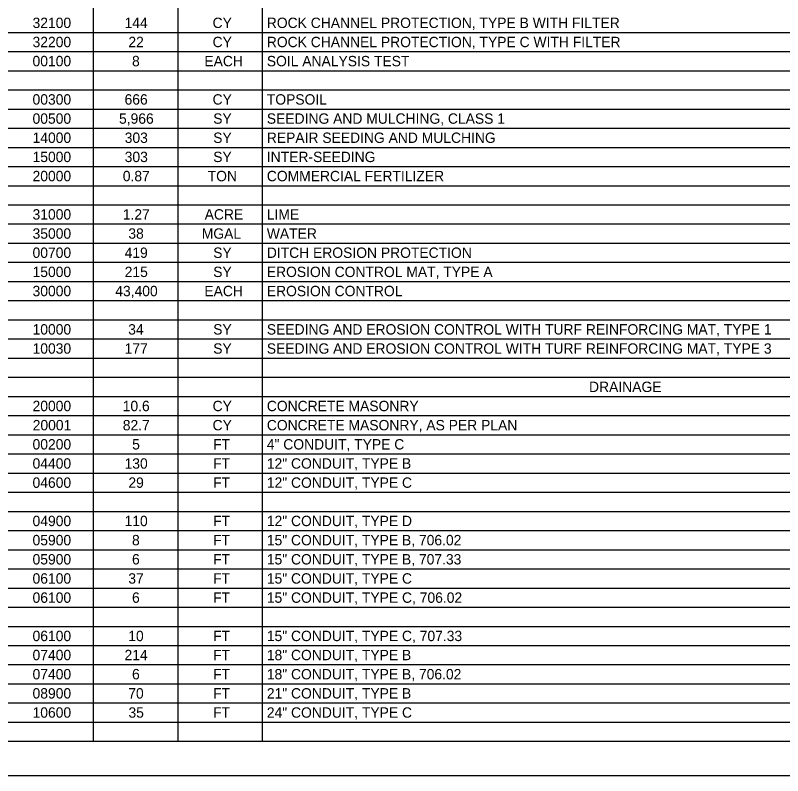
# Model space of a CAD drawing. Extents: x 0 to 34, y 0 to 22.
# Drawn here: x 16.9 to 28.11, y 0 to 11.11 of the extents above; entities that cross this region are included whole.
import ezdxf

# ---------------------------------------------------------------- set-up
doc = ezdxf.new("R2010")
doc.units = 0
for name, color, linetype in [('Default', 7, 'Continuous'), ('SH_Border', 7, 'Continuous'), ('SH_Cut_Line', 7, 'Continuous')]:
    doc.layers.add(name, color=color, linetype=linetype)

msp = doc.modelspace()

# ---------------------------------------------------------------- linework, layer by layer
at = {"layer": 'Default'}
for p, q in [((18.035, 21.5), (18.035, 0.502)), ((19.27, 21.5), (19.27, 0.502)), ((20.505, 21.5), (20.505, 0.502)), ((1.5, 10.861), (32, 10.861)), ((1.5, 10.581), (32, 10.581)), ((1.5, 10.301), (32, 10.301)), ((1.5, 10.021), (32, 10.021)), ((1.5, 9.741), (32, 9.741)), ((1.5, 9.461), (32, 9.461)), ((1.5, 9.181), (32, 9.181)), ((1.5, 8.901), (32, 8.901)), ((1.5, 8.621), (32, 8.621)), ((1.5, 8.342), (32, 8.342)), ((1.5, 8.062), (32, 8.062)), ((1.5, 7.782), (32, 7.782)), ((1.5, 7.502), (32, 7.502)), ((1.5, 7.222), (32, 7.222)), ((1.5, 6.942), (32, 6.942)), ((1.5, 6.662), (32, 6.662)), ((1.5, 6.382), (32, 6.382)), ((1.5, 6.102), (32, 6.102)), ((1.5, 5.822), (32, 5.822)), ((1.5, 5.542), (32, 5.542)), ((1.5, 5.262), (32, 5.262)), ((1.5, 4.982), (32, 4.982)), ((1.5, 4.702), (32, 4.702)), ((1.5, 4.422), (32, 4.422)), ((1.5, 4.142), (32, 4.142)), ((1.5, 3.862), (32, 3.862)), ((1.5, 3.582), (32, 3.582)), ((1.5, 3.302), (32, 3.302)), ((1.5, 3.022), (32, 3.022)), ((1.5, 2.742), (32, 2.742)), ((1.5, 2.462), (32, 2.462)), ((1.5, 2.182), (32, 2.182)), ((1.5, 1.902), (32, 1.902)), ((1.5, 1.622), (32, 1.622)), ((1.5, 1.342), (32, 1.342)), ((1.5, 1.062), (32, 1.062)), ((1.5, 0.782), (32, 0.782)), ((1.5, 0.502), (32, 0.502))]:
    msp.add_line(p, q, dxfattribs=at)
at = {"layer": 'SH_Border'}
msp.add_lwpolyline([(1.5, 21.5), (33.5, 21.5), (33.5, 0.5), (1.5, 0.5)], close=True, dxfattribs=at)
at = {"layer": 'SH_Cut_Line'}
msp.add_lwpolyline([(0, 0), (34, 0), (34, 22), (0, 22)], close=True, dxfattribs=at)

# ---------------------------------------------------------------- texts
at = {"layer": 'Default'}
for s, height, p in [('32100', 0.1515, (17.149, 10.925)), ('144', 0.1515, (18.492, 10.925)), ('CY', 0.1515, (19.779, 10.925)), ('ROCK CHANNEL PROTECTION, TYPE B WITH FILTER', 0.15151, (20.571, 10.925)), ('32200', 0.1515, (17.149, 10.645)), ('22', 0.1515, (18.549, 10.645)), ('CY', 0.1515, (19.779, 10.645)), ('ROCK CHANNEL PROTECTION, TYPE C WITH FILTER', 0.15151, (20.571, 10.645)), ('00100', 0.1515, (17.149, 10.366)), ('8', 0.152, (18.602, 10.366)), ('EACH', 0.1515, (19.659, 10.366)), ('SOIL ANALYSIS TEST', 0.15151, (20.571, 10.366)), ('00300', 0.1515, (17.149, 9.806)), ('666', 0.1515, (18.493, 9.806)), ('CY', 0.1515, (19.779, 9.806)), ('TOPSOIL', 0.1515, (20.571, 9.806)), ('00500', 0.1515, (17.149, 9.526)), ('5,966', 0.1515, (18.412, 9.526)), ('SY', 0.1515, (19.788, 9.526)), ('SEEDING AND MULCHING, CLASS 1', 0.15151, (20.571, 9.526)), ('14000', 0.1515, (17.149, 9.246)), ('303', 0.1515, (18.495, 9.246)), ('SY', 0.1515, (19.788, 9.246)), ('REPAIR SEEDING AND MULCHING', 0.15151, (20.571, 9.246)), ('15000', 0.1515, (17.149, 8.966)), ('303', 0.1515, (18.495, 8.966)), ('SY', 0.1515, (19.788, 8.966)), ('INTER-SEEDING', 0.15151, (20.571, 8.966)), ('20000', 0.1515, (17.149, 8.686)), ('0.87', 0.1515, (18.467, 8.686)), ('TON', 0.1515, (19.707, 8.686)), ('COMMERCIAL FERTILIZER', 0.15151, (20.571, 8.686)), ('31000', 0.1515, (17.149, 8.126)), ('1.27', 0.1515, (18.467, 8.126)), ('ACRE', 0.1515, (19.663, 8.126)), ('LIME', 0.1515, (20.571, 8.126)), ('35000', 0.1515, (17.149, 7.846)), ('38', 0.1515, (18.548, 7.846)), ('MGAL', 0.1515, (19.621, 7.846)), ('WATER', 0.1515, (20.571, 7.846)), ('00700', 0.1515, (17.149, 7.566)), ('419', 0.1515, (18.494, 7.566)), ('SY', 0.1515, (19.788, 7.566)), ('DITCH EROSION PROTECTION', 0.15151, (20.571, 7.566)), ('15000', 0.1515, (17.149, 7.286)), ('215', 0.1515, (18.495, 7.286)), ('SY', 0.1515, (19.788, 7.286)), ('EROSION CONTROL MAT, TYPE A', 0.15151, (20.571, 7.286)), ('30000', 0.1515, (17.149, 7.006)), ('43,400', 0.1515, (18.357, 7.006)), ('EACH', 0.1515, (19.659, 7.006)), ('EROSION CONTROL', 0.15151, (20.571, 7.006)), ('10000', 0.1515, (17.149, 6.446)), ('34', 0.1515, (18.546, 6.446)), ('SY', 0.1515, (19.788, 6.446)), ('SEEDING AND EROSION CONTROL WITH TURF REINFORCING MAT, TYPE 1', 0.15151, (20.571, 6.446)), ('10030', 0.1515, (17.149, 6.166)), ('177', 0.1515, (18.494, 6.166)), ('SY', 0.1515, (19.788, 6.166)), ('SEEDING AND EROSION CONTROL WITH TURF REINFORCING MAT, TYPE 3', 0.15151, (20.571, 6.166)), ('DRAINAGE', 0.1515, (25.278, 5.606)), ('20000', 0.1515, (17.149, 5.326)), ('10.6', 0.1515, (18.466, 5.326)), ('CY', 0.1515, (19.779, 5.326)), ('CONCRETE MASONRY', 0.15151, (20.571, 5.326)), ('20001', 0.1515, (17.151, 5.046)), ('82.7', 0.1515, (18.467, 5.046)), ('CY', 0.1515, (19.779, 5.046)), ('CONCRETE MASONRY, AS PER PLAN', 0.15151, (20.571, 5.046)), ('00200', 0.1515, (17.149, 4.766)), ('5', 0.152, (18.604, 4.766)), ('FT', 0.1515, (19.786, 4.766)), ('4" CONDUIT, TYPE C', 0.15151, (20.571, 4.766)), ('04400', 0.1515, (17.149, 4.486)), ('130', 0.1515, (18.493, 4.486)), ('FT', 0.1515, (19.786, 4.486)), ('12" CONDUIT, TYPE B', 0.15151, (20.571, 4.486)), ('04600', 0.1515, (17.149, 4.206)), ('29', 0.1515, (18.549, 4.206)), ('FT', 0.1515, (19.786, 4.206)), ('12" CONDUIT, TYPE C', 0.15151, (20.571, 4.206)), ('04900', 0.1515, (17.149, 3.646)), ('110', 0.1515, (18.493, 3.646)), ('FT', 0.1515, (19.786, 3.646)), ('12" CONDUIT, TYPE D', 0.15151, (20.571, 3.646)), ('05900', 0.1515, (17.149, 3.366)), ('8', 0.152, (18.602, 3.366)), ('FT', 0.1515, (19.786, 3.366)), ('15" CONDUIT, TYPE B, 706.02', 0.15151, (20.571, 3.366)), ('05900', 0.1515, (17.149, 3.086)), ('6', 0.152, (18.602, 3.086)), ('FT', 0.1515, (19.786, 3.086)), ('15" CONDUIT, TYPE B, 707.33', 0.15151, (20.571, 3.086)), ('06100', 0.1515, (17.149, 2.806)), ('37', 0.1515, (18.548, 2.806)), ('FT', 0.1515, (19.786, 2.806)), ('15" CONDUIT, TYPE C', 0.15151, (20.571, 2.806)), ('06100', 0.1515, (17.149, 2.526)), ('6', 0.152, (18.602, 2.526)), ('FT', 0.1515, (19.786, 2.526)), ('15" CONDUIT, TYPE C, 706.02', 0.15151, (20.571, 2.526)), ('06100', 0.1515, (17.149, 1.966)), ('10', 0.1515, (18.547, 1.966)), ('FT', 0.1515, (19.786, 1.966)), ('15" CONDUIT, TYPE C, 707.33', 0.15151, (20.571, 1.966)), ('07400', 0.1515, (17.149, 1.687)), ('214', 0.1515, (18.492, 1.687)), ('FT', 0.1515, (19.786, 1.687)), ('18" CONDUIT, TYPE B', 0.15151, (20.571, 1.687)), ('07400', 0.1515, (17.149, 1.407)), ('6', 0.152, (18.602, 1.407)), ('FT', 0.1515, (19.786, 1.407)), ('18" CONDUIT, TYPE B, 706.02', 0.15151, (20.571, 1.407)), ('08900', 0.1515, (17.149, 1.127)), ('70', 0.1515, (18.547, 1.127)), ('FT', 0.1515, (19.786, 1.127)), ('21" CONDUIT, TYPE B', 0.15151, (20.571, 1.127)), ('10600', 0.1515, (17.149, 0.847)), ('35', 0.1515, (18.55, 0.847)), ('FT', 0.1515, (19.786, 0.847)), ('24" CONDUIT, TYPE C', 0.15151, (20.571, 0.847))]:
    msp.add_text(s, height=height, dxfattribs=at).set_placement(p)

doc.saveas('drawing.dxf')
